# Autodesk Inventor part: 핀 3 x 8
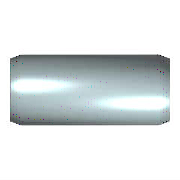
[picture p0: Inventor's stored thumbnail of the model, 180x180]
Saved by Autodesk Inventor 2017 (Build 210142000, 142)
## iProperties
IsCustomPart: 1
Created: 2012-02
Part Number: 핀 3 x 8
Material: 강철, 연강
Description: 평행 핀
Document SubType Name: Modeling
Standard: KS B 1320
Designer: mduedu
Standards Organization: KS
Language: ko-KR
Size Designation: B 3 x  8
Categories: <MemberInstance><Categories><Category DisplayName="조임쇠" InternalName="e4da775c-781d-43d5-af7c-5136215cf5a6" Mnemonic="FSTN"><Category DisplayName="핀" InternalNa
Density: 7.85 g/cm^3
Appearance: 노란색
Mass: 0.439099 g
Surface Area: 0.870195 cm^2
Volume: 0.0559361 cm^3
Author: mduedu
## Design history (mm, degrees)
sketch "스케치"
  geometry: C1 r 1.5 at (0, 0); 1 further point
  constraints: 1 centre point, 1 coincident
  dimensions: "d1" = 3 diameter of C1 (= NND)
extrude "본체" new body sketch "스케치" distance "d2" = 8 (= NLG); taper "d3" = 0 deg
chamfer "스케치2" distance "d8" = 0.5 (= PHH); stored, may be unused: angle "d9" = 15 deg (= FAWI), second distance "d12" = 0.5 (= PHH)
body "Solid1"
chamfer "모따기1" distance "d4" = 0.5 (= PHH); stored, may be unused: angle "d5" = 15 deg (= FAWI), second distance "d11" = 0.5 (= PHH)
other parameters: "NND" = 3 [user parameter; used in 1 equation term], "NLG" = 8 [user parameter; used in 1 equation term], "PHH" = 0.5 [user parameter; used in 4 equation terms], "FAWI" = 15 deg [user parameter; used in 2 equation terms], "d13" = 0, "d15" = 0, "d16" = 0, "KAH" = 0.4 [user parameter]
